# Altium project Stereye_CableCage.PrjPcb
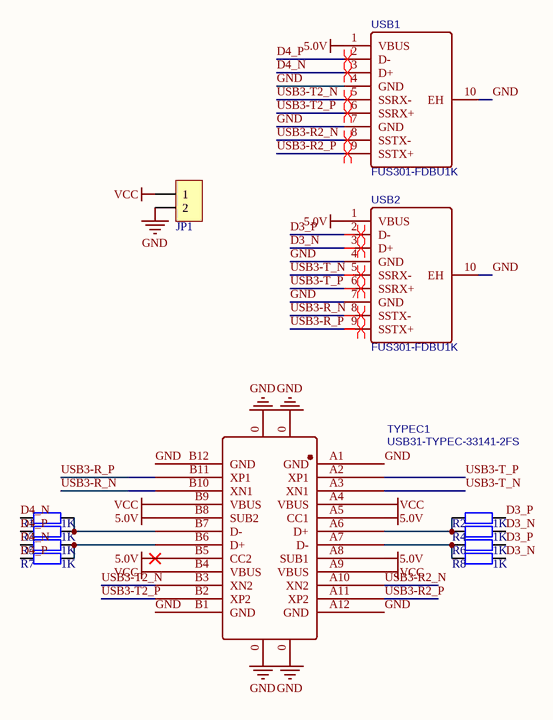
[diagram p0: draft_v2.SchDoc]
1 sheet, 12 parts. Net scope: global (net labels, ports and power ports of the same name join across sheets).
Board file: CablecageV5.PcbDoc

## Sheet draft_v2.SchDoc
size A4

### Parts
JP1  HDR-1X2  [XT30]  (value not drawn)
R1  1K  [R 0603_L]
R2  1K  [R 0603_L]
R3  1K  [R 0603_L]
R4  1K  [R 0603_L]
R5  1K  [R 0603_L]
R6  1K  [R 0603_L]
R7  1K  [R 0603_L]
R8  1K  [R 0603_L]
TYPEC1  USB31-TYPEC-33141-2FS  [USB-C-SMD_TYPEC-501S-ACP24H104]
USB1  FUS301-FDBU1K  [USB3.0-male-0.8d]
USB2  FUS301-FDBU1K  [USB3.0-male-0.8d]

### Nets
5.0V: TYPEC1.A5(CC1) TYPEC1.A8(SUB1) TYPEC1.B5(CC2) TYPEC1.B8(SUB2) USB1.1(VBUS) USB2.1(VBUS)
GND: JP1.2 TYPEC1.0 TYPEC1.A1(GND) TYPEC1.A12(GND) TYPEC1.B1(GND) TYPEC1.B12(GND) USB1.4(GND) USB1.7(GND) USB1.10(EH) USB2.4(GND) USB2.7(GND) USB2.10(EH)
VCC: JP1.1 TYPEC1.A4(VBUS) TYPEC1.A9(VBUS) TYPEC1.B4(VBUS) TYPEC1.B9(VBUS)
D3_N: R4.2 R8.2 USB2.3(D+)
D3_P: R2.2 R6.2 USB2.2(D-)
D4_N: R1.1 R5.1 USB1.3(D+)
D4_P: R3.1 R7.1 USB1.2(D-)
USB3-R2_N: TYPEC1.A10(XN2) USB1.8(SSTX-)
USB3-R2_P: TYPEC1.A11(XP2) USB1.9(SSTX+)
USB3-R_N: TYPEC1.B10(XN1) USB2.8(SSTX-)
USB3-R_P: TYPEC1.B11(XP1) USB2.9(SSTX+)
USB3-T2_N: TYPEC1.B3(XN2) USB1.5(SSRX-)
USB3-T2_P: TYPEC1.B2(XP2) USB1.6(SSRX+)
USB3-T_N: TYPEC1.A3(XN1) USB2.5(SSRX-)
USB3-T_P: TYPEC1.A2(XP1) USB2.6(SSRX+)
NetR1_2: R1.2 R3.2 TYPEC1.B7(D-)
NetR2_1: R2.1 R4.1 TYPEC1.A6(D+)
NetR5_2: R5.2 R7.2 TYPEC1.B6(D+)
NetR6_1: R6.1 R8.1 TYPEC1.A7(D-)

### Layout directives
differential pair: D3_N, D3_P, D4_N, D4_P, USB3-R2_N, USB3-R2_P, USB3-R_N, USB3-R_P, USB3-T2_N, USB3-T2_P, USB3-T_N, USB3-T_P

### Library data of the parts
JP1 = Header 2: 2P接插件; 版权归属: 封装库来自淘宝 ID：黄晶宝石
R1-R8 = R: 贴片电阻; 版权归属: 来自淘宝 ID：黄晶宝石
TYPEC1 = USB31-TYPEC-33141-2FS: BOM_Manufacturer: XKB Enterprise; Contributor: LCSC
USB1 USB2 = FUS301-FDBU1K: BOM_Manufacturer: TXGA; Contributor: LCSC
